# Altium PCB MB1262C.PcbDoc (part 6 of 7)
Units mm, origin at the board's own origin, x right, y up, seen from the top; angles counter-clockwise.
Board outline 208 x 250 mm, 6 copper layers (Top Layer, Layer 2, Layer 3, Layer 4, Layer 5, Bottom Layer), stack 1.596 mm thick; 483 components, 502 nets, 2134 pads, 1709 vias.
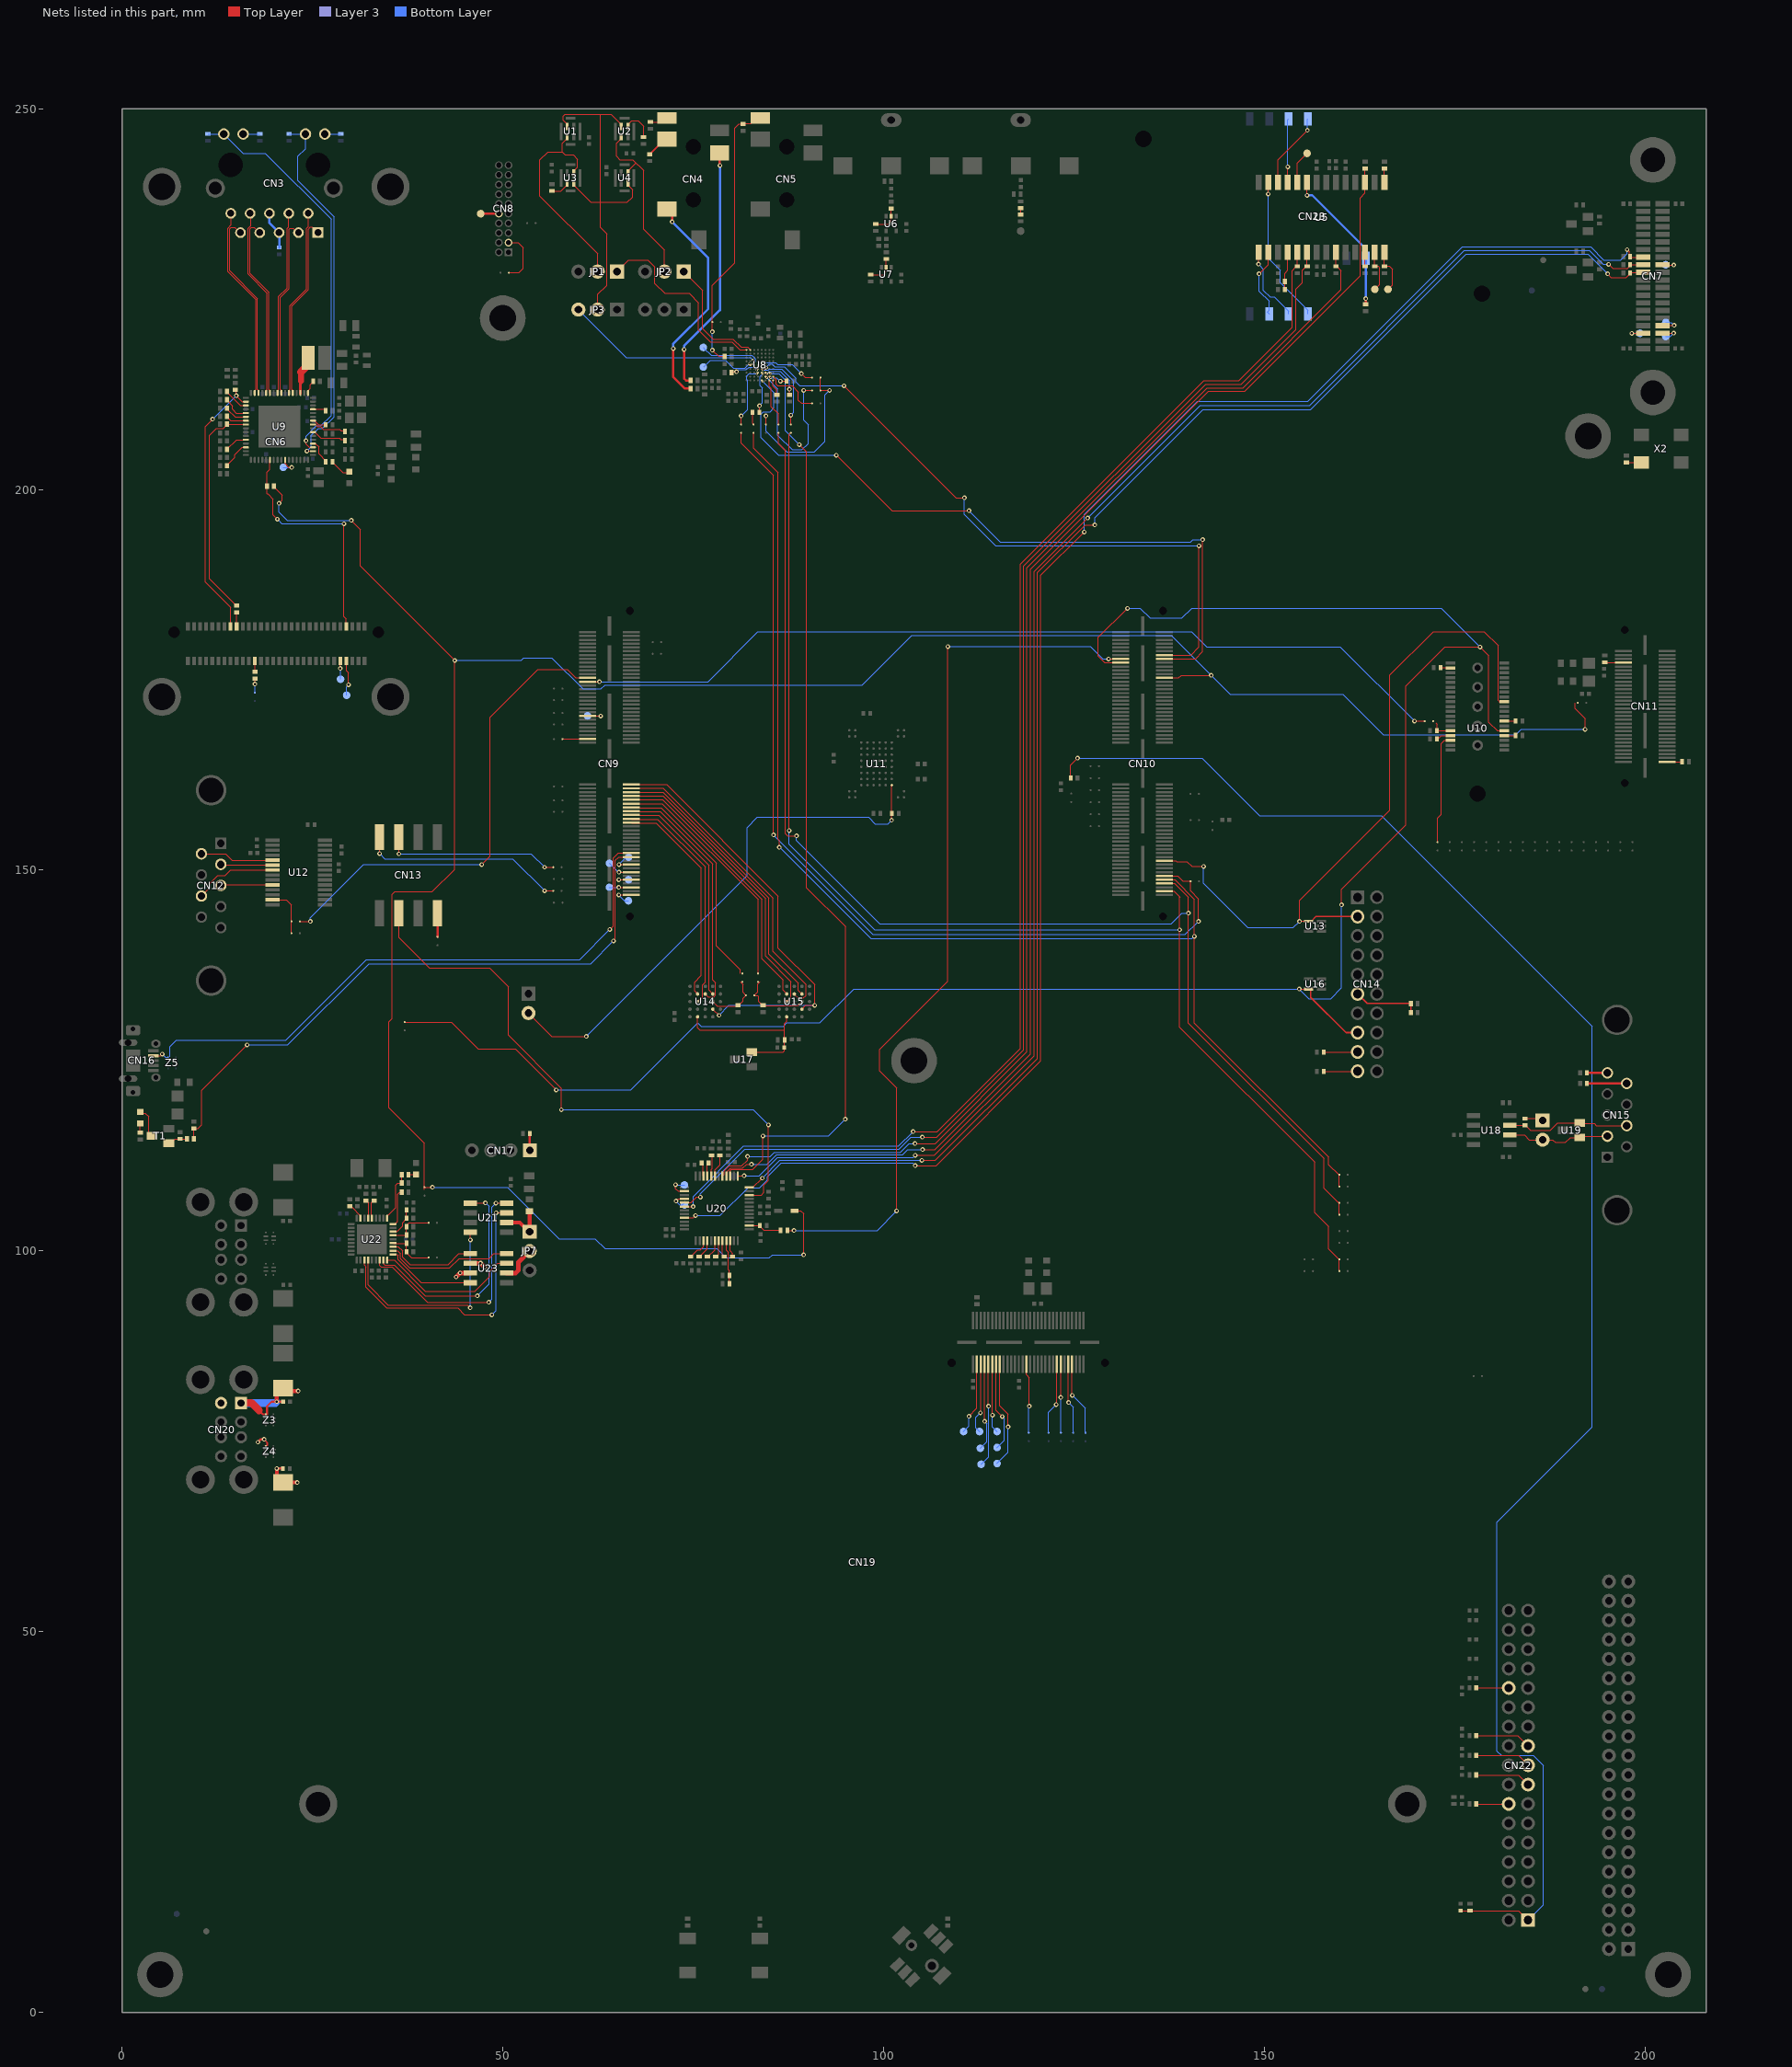
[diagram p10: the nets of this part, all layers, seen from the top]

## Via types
v1: diameter 0.6, hole 0.3, Top Layer to Bottom Layer, tented both sides, 979 vias
v2: diameter 0.55, hole 0.3, Top Layer to Bottom Layer, tented both sides, 687 vias
v3: diameter 0.3, hole 0.15, Top Layer to Bottom Layer, tented both sides, 31 vias
v4: diameter 0.4, hole 0.2, Top Layer to Bottom Layer, tented both sides, 12 vias

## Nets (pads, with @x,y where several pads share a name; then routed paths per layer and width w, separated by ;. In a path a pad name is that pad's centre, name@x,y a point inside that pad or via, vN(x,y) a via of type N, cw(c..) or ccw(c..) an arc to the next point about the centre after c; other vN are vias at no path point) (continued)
NetC102_1: C102.1 C105.2 CN20.T1 U23.7 Z3.1 | length 18.4
  Top Layer w0.1: v1(43.858,96.584) v1@43.858,96.6 ; v1(44.387,97.128) v1@44.401,97.114
  Top Layer w0.25: 17.97,79.08 18.488,78.562 Z3.1@18.892,78.562 ; 19.042,78.589 19.042,79.594 19.662,80.215 v1@20.33,80.215 ; v1(20.315,80.215) 20.318,80.219 C105.2@21.163,80.219
  Top Layer w0.5: v1@20.307,80.224 20.307,81.131 C102.1@21.17,81.995 21.555,81.609 23.121,81.609 v1(23.121,81.618)
  Top Layer w0.6: v1@43.858,96.6 v1(44.387,97.128) ; v1@44.401,97.114 U23.7@45.74,97.114
  Top Layer w1: CN20.T1@15.632,80.057 16.993,80.057 17.97,79.08
  Bottom Layer w1: CN20.T1@15.63,80.05 20.145,80.05 v1@20.285,80.19
NetC106_2: C106.2 C107.1 CN20.B1 U23.6 Z4.1 | length 9.4
  Top Layer w0.1: C107.1@20.321,70.462 C107.1@21.17,69.612 ; v1@47.076,98.384 v1(47.09,98.398) ; v1@47.636,97.852 v1(47.644,97.852)
  Top Layer w0.2: v1(18.664,75.271) 19.075,74.859 19.075,74.527 ; Z4.1@18.833,74.438 18.986,74.438 19.035,74.487 ; 19.075,74.68 19.075,74.527 ; 19.035,74.487 19.075,74.527 ; 19.035,74.487 19.075,74.487 19.075,74.527
  Top Layer w0.3: v1(17.852,74.901) 18.223,75.271 v1(18.664,75.271) ; v1(20.321,71.435) C106.2@21.119,71.435
  Top Layer w0.5: C107.1@20.321,70.462 v1(20.321,71.435) ; C107.1@21.17,69.612 v1(22.996,69.612)
  Top Layer w0.6: U23.6@45.74,98.384 v1@47.076,98.384 ; v1(47.09,98.398) v1@47.636,97.852
  Layer 3 w0.1: v1(47.09,98.398) v1@47.107,98.381
NetC118_2: C118.2 CN22.1 R83.2 R137.1 | length 222.8
  Top Layer w0.13: R83.2@124.559,162.096 124.559,163.811 v1(125.455,164.708) ; C118.2@175.731,13.369 C118.2@175.747,13.385 R137.1@176.98,13.385 183.39,13.385 CN22.1@184.62,12.155
  Bottom Layer w0.13: v1(125.455,164.708) 125.457,164.706 141.81,164.706 149.389,157.127 165.362,157.127 193.004,129.485 193.004,76.865 180.556,64.417 180.556,34.336 181.123,33.77 185.294,33.77 186.625,32.439 186.625,14.16 CN22.1@184.62,12.155
NetC120_2: C120.2 CN3.5 CN3.6 | length 5
  Bottom Layer w0.1: CN3.5@20.635,233.71 CN3.5@20.646,233.699
  Bottom Layer w0.3: CN3.6@19.365,236.25 19.365,234.98 CN3.5@20.635,233.71 ; C120.2@20.646,231.766 CN3.5@20.646,233.699
NetCN3_11: CN3.11 R140.1 | length 2.1
  Bottom Layer w0.1: CN3.11@26.63,246.66 26.65,246.68 R140.1@28.722,246.68
NetCN3_12: CN3.12 R141.2 U9.50 | length 48.8
  Top Layer w0.1: v1(24.282,205.032) 24.289,205.025 U9.50@25.075,205.025
  Bottom Layer w0.1: R141.2@21.929,246.68 24.07,246.68 CN3.12@24.09,246.66 24.09,244.744 23.078,243.732 23.078,240.558 27.833,235.803 27.833,209.54 26.316,208.023 25.776,208.023 24.83,207.076 24.83,205.58 v1(24.282,205.032)
NetCN3_13: CN3.13 R143.1 | length 2.2
  Bottom Layer w0.1: CN3.13@15.91,246.66 15.923,246.673 R143.1@18.096,246.673
NetCN3_14: CN3.14 R142.2 U9.51 | length 53.1
  Top Layer w0.1: v1(24.163,206.392) 24.163,205.977 24.615,205.525 U9.51@25.075,205.525
  Bottom Layer w0.1: R142.2@11.285,246.673 13.357,246.673 CN3.14@13.37,246.66 15.885,244.145 18.806,244.145 27.465,235.485 27.465,209.714 26.117,208.365 25.524,208.365 24.163,207.004 v1(24.163,206.392)
NetCN4_2: CN4.2 R1.2 | length 2.4
  Top Layer w0.127: R1.2@69.359,248.254 69.362,248.251 71.051,248.251 CN4.2@71.55,248.75
NetCN4_3: CN4.3 R4.1 | length 3.1
  Top Layer w0.2: R4.1@69.291,243.998 R4.1@69.297,244.004 ; R4.1@69.291,244.01 71.28,246 CN4.3@71.55,246
NetCN4_4: CN4.4 R42.2 | length 32.6
  Top Layer w0.2: CN4.4@78.45,244.2 CN4.4@78.493,244.157 ; v1@78.493,242.541 v1(78.507,242.527)
  Top Layer w0.3: v1(73.794,218.391) 73.794,214.571 74.052,214.313 R42.2@74.654,214.313 ; v1@78.493,242.541 CN4.4@78.493,244.157
  Bottom Layer w0.3: v1(73.794,218.391) 73.794,218.828 78.507,223.541 v1(78.507,242.527)
NetCN4_6: CN4.6 R46.2 | length 29.1
  Top Layer w0.2: CN4.6@71.55,236.8 CN4.6@72.215,236.135
  Top Layer w0.3: v1(72.215,235.138) CN4.6@72.215,236.135 ; v1(72.389,218.489) 72.389,214.756 73.907,213.238 R46.2@74.654,213.238
  Bottom Layer w0.3: v1(72.215,235.138) 76.967,230.387 76.967,223.707 72.389,219.129 v1(72.389,218.489)
NetCN5_2: CN5.2 R2.1 R35.2 SB3.1 | length 36.1
  Top Layer w0.127: v1(77.508,220.706) SB3.1@77.508,221.965 77.508,226.782 80.471,229.745 80.471,247.455 80.989,247.973 R2.1@81.535,247.973 81.6,248.038 82.578,248.038 83.125,248.585 CN5.2@83.811,248.585 ; v1(77.523,218.297) 78.346,217.475 R35.2@79.125,217.475
  Bottom Layer w0.127: v1(77.508,220.706) 77.523,220.691 v1(77.523,218.297)
NetCN6_18: CN6.18 R74.2 | length 1.9
  Top Layer w0.1: R74.2@15.046,183.861 15.051,183.856 15.051,182.001 CN6.18@15.05,182
NetCN6_23: CN6.23 R77.2 | length 1.4
  Top Layer w0.1: CN6.23@17.45,177.5 17.457,177.493 R77.2@17.457,176.065
NetCN6_51: CN6.51 TP13.1 | length 2.4
  Top Layer w0.1: v1(28.65,176.501) CN6.51@28.65,177.5
  Bottom Layer w0.1: v1(28.65,176.501) 28.7,176.451 TP13.1@28.7,175.075
NetCN6_53: CN6.53 TP14.1 | length 4.8
  Top Layer w0.1: CN6.53@29.45,177.5 29.473,177.523 CN6.53@29.522,177.474 ; CN6.53@29.479,177.431 29.479,176.19 29.756,175.913 v1(29.756,174.342)
  Bottom Layer w0.1: TP14.1@29.5,172.975 29.5,174.079 v1@29.771,174.349
NetCN7_15: CN7.15 R19.2 U20.33 | length 220.2
  Top Layer w0.1: U20.33@73.872,104.328 U20.33@73.85,104.35 75.007,104.35 v1(75.307,104.65) ; v1(104.138,111.221) 106.881,111.221 120.644,124.984 120.644,188.712 v1(126.343,194.411) ; v1(197.617,231.494) 197.931,231.179 197.931,230.669 R19.2@198.025,230.575 198.1,230.5 CN7.15@199.725,230.5
  Bottom Layer w0.1: v1(75.307,104.65) 78.508,104.65 82.183,108.325 83.699,108.325 84.729,109.355 84.729,109.738 86.531,111.54 103.819,111.54 v1(104.138,111.221) ; v1(126.343,194.411) 126.343,196.693 141.219,211.569 155.725,211.569 175.997,231.841 192.824,231.841 194.561,230.104 196.77,230.104 197.617,230.951 v1(197.617,231.494)
NetCN7_17: CN7.17 R21.2 U20.13 | length 207.7
  Top Layer w0.1: U20.13@80.85,109.85 80.889,109.889 80.896,109.882 v1(81.69,109.882) ; v1(104.159,112.57) 106.686,112.57 119.751,125.635 119.751,189.21 v1(126.797,196.256) ; v1(195.178,229.541) 195.719,229 197.604,229 197.624,228.98 198.025,229.381 R21.2@198.025,229.5 CN7.17@199.725,229.5
  Bottom Layer w0.1: v1(81.69,109.882) 83.666,109.882 86.082,112.298 103.887,112.298 v1(104.159,112.57) ; v1(126.797,196.256) 141.594,211.053 155.938,211.053 176.247,231.362 192.648,231.362 194.469,229.541 v1(195.178,229.541)
NetCN7_18: CN7.18 TP6.1 | length 2.6
  Top Layer w0.1: CN7.18@202.275,229.5 202.321,229.454 v1(203.749,229.454)
  Bottom Layer w0.1: TP6.1@202.675,229.5 202.721,229.454 v1(203.749,229.454)
NetCN7_19: CN7.19 R28.2 U20.12 | length 207.7
  Top Layer w0.1: U20.12@82.35,108.35 82.837,108.35 v1(84.053,109.566) ; v1(105.017,111.904) 106.81,111.904 120.204,125.298 120.204,189.087 126.455,195.339 v1(127.719,195.339) ; v1(195.074,228.301) 195.074,228.268 195.529,227.814 197.496,227.814 198.025,228.343 R28.2@198.025,228.425 198.1,228.5 CN7.19@199.725,228.5
  Bottom Layer w0.1: v1(84.053,109.566) 86.392,111.904 v1(105.017,111.904) ; v1(127.719,195.339) 127.719,196.288 141.91,210.479 156.052,210.479 176.483,230.911 192.464,230.911 v1(195.074,228.301)
NetCN7_34: CN7.34 TP7.1 | length 2.8
  Top Layer w0.1: CN7.34@202.275,221.5 202.315,221.54 v1(203.806,221.54)
  Bottom Layer w0.1: TP7.1@202.7,221.925 203.421,221.925 v1(203.806,221.54)
NetCN7_35: CN7.35 TP8.1 | length 2.5
  Top Layer w0.1: v1(198.247,220.483) 199.708,220.483 CN7.35@199.725,220.5
  Bottom Layer w0.1: v1(198.247,220.483) 198.265,220.5 TP8.1@199.3,220.5
NetCN7_36: CN7.36 TP9.1 | length 2.7
  Top Layer w0.1: CN7.36@202.275,220.5 202.299,220.524 v1(203.726,220.524)
  Bottom Layer w0.1: TP9.1@202.7,220.075 203.278,220.075 v1(203.726,220.524)
NetCN8_3: CN8.3 SB2.2 | length 7.1
  Top Layer w0.1: CN8.3@50.736,232.398 52.015,232.398 52.689,231.724 52.689,229.017 52.132,228.46 SB2.2@50.797,228.46
NetCN8_10: CN8.10 TP2.1 | length 2.3
  Top Layer w0.3: TP2.1@47.22,236.216 CN8.10@49.482,236.216
NetCN9_45: CN9.45 TP15.1 | length 3.5
  Top Layer w0.1: CN9.45@61.13,170.25 v1(62.853,170.25)
  Bottom Layer w0.1: TP15.1@61.125,170.275 62.828,170.275 v1(62.853,170.25)
NetCN9_104: CN9.104 TP16.1 | length 3.3
  Top Layer w0.1: v1(65.25,150.75) CN9.104@66.87,150.75
  Bottom Layer w0.1: v1@65.25,150.728 66.226,151.703 TP16.1@66.508,151.703
NetCN9_108: CN9.108 TP17.1 | length 3.4
  Top Layer w0.1: v1(65.247,149.75) CN9.108@66.87,149.75
  Bottom Layer w0.1: TP17.1@63.991,150.92 65.171,149.74 v1@65.266,149.74
NetCN9_112: CN9.112 TP18.1 | length 2.9
  Top Layer w0.1: v1(65.234,148.749) CN9.112@66.87,148.75
  Bottom Layer w0.1: v1@65.226,148.76 65.233,148.752 TP18.1@66.508,148.752
NetCN9_116: CN9.116 TP19.1 | length 2.9
  Top Layer w0.1: v1(65.233,147.75) CN9.116@66.87,147.75
  Bottom Layer w0.1: TP19.1@63.991,147.752 65.221,147.752 v1@65.234,147.74
NetCN9_120: CN9.120 TP20.1 | length 3.2
  Top Layer w0.1: v1(65.23,146.75) CN9.120@66.87,146.75
  Bottom Layer w0.1: v1@65.226,146.727 65.968,145.985 TP20.1@66.492,145.985
NetCN10_26: CN10.26 D1.2 R73.1 SB16.1 SB64.1 | length 345.4
  Top Layer w0.1: R73.1@19.936,200.412 19.936,200.362 21.044,199.254 21.044,198.601 v1(20.622,198.18) ; v1(30.096,195.94) 31.3,194.736 31.3,189.925 v1(43.686,177.539) 43.686,150.112 40.738,147.163 35.824,147.163 35.487,146.827 35.487,130.521 35.066,130.099 35.066,118.783 39.7,114.149 SB64.1@39.7,108.375 ; 39.7,108.075 SB64.1@39.7,108.375 ; v1(40.775,108.375) SB64.1@39.7,108.375 ; D1.2@88.32,105.3 89.1,105.3 89.5,104.9 v1(89.5,99.5) ; CN10.26@136.87,175.25 138.75,175.25 139.1,175.6 v1(143,175.6) ; 190.775,171.95 190.775,171.248 192.1,169.923 v1(192.1,168.5)
  Bottom Layer w0.1: v1(20.622,198.18) 20.622,197.042 21.712,195.953 30.083,195.953 v1(30.096,195.94) ; v1(40.775,108.375) 50.625,108.375 57.4,101.6 62.1,101.6 63.4,100.3 78.1,100.3 79.3,99.1 85,99.1 85.4,99.5 v1(89.5,99.5) ; v1(43.686,177.539) 52.423,177.539 52.735,177.851 56.449,177.851 60.5,173.8 62.9,173.8 63.4,174.3 97.2,174.3 103.7,180.8 137.8,180.8 145.5,173.1 160.3,173.1 165.6,167.8 183,167.8 183.7,168.5 v1(192.1,168.5)
NetCN11_1: CN11.1 R82.1 | length 2
  Top Layer w0.1: CN11.1@202.87,164.25 R82.1@204.85,164.25
NetCN11_54: CN11.54 R75.2 | length 2.5
  Top Layer w0.1: R75.2@194.675,177.3 194.725,177.25 CN11.54@197.13,177.25
NetCN12_2: CN12.2 U12.6 | length 6.8
  Top Layer w0.1: CN12.2@12.97,150.77 13.065,150.675 U12.6@19.75,150.675
NetCN12_3: CN12.3 U12.10 | length 6.8
  Top Layer w0.1: CN12.3@12.97,148 13.045,148.075 U12.10@19.75,148.075
NetCN12_6: CN12.6 U12.5 | length 9.7
  Top Layer w0.1: CN12.6@10.43,152.155 13.617,152.155 14.447,151.325 U12.5@19.75,151.325
NetCN12_8: CN12.8 U12.7 | length 11
  Top Layer w0.1: CN12.8@10.43,146.615 11.494,147.679 11.494,148.203 12.587,149.296 13.518,149.296 14.247,150.025 U12.7@19.75,150.025
NetCN13_1: CN13.1 SB54.2 | length 27
  Top Layer w0.1: v1(33.815,152.185) CN13.1@33.815,154.35 ; v1(55.486,147.292) SB54.2@56.617,147.292
  Bottom Layer w0.1: v1(33.815,152.185) 34.5,151.5 51.278,151.5 v1(55.486,147.292)
NetCN13_3: CN13.3 SB51.2 | length 23.2
  Top Layer w0.1: v1(36.355,152.145) CN13.3@36.355,154.35 ; v1(55.486,150.392) SB51.2@56.617,150.392
  Bottom Layer w0.1: v1(36.355,152.145) 53.732,152.145 v1(55.486,150.392)
NetCN13_4: CN13.4 U20.10 | length 78.5
  Top Layer w0.1: CN13.4@36.355,144.35 36.355,141.175 40.382,137.147 48.261,137.147 50.741,134.667 50.741,128.321 57.689,121.373 v1(57.689,118.554) ; U20.10@82.35,107.35 83.949,107.35 84.277,107.678 84.277,108.678 84.872,109.274 v1(84.872,116.568)
  Bottom Layer w0.1: v1(57.689,118.554) 82.885,118.554 v1(84.872,116.568)
NetCN13_8: CN13.8 SB58.1 | length 3.1
  Top Layer w0.1: CN13.8@41.425,144.34 CN13.8@41.435,144.35
  Top Layer w0.3: SB58.1@41.425,141.25 CN13.8@41.425,144.34
NetCN14_11: CN14.11 R86.2 R89.1 | length 8.7
  Top Layer w0.2: CN14.11@162.23,133.755 163.485,132.5 R86.2@169.225,132.5 R89.1@169.225,131.3
NetCN14_17: CN14.17 R91.1 | length 4.5
  Top Layer w0.1: R91.1@157.775,126.125 162.22,126.125 CN14.17@162.23,126.135
NetCN14_19: CN14.19 R92.1 | length 4.5
  Top Layer w0.1: R92.1@157.775,123.575 162.21,123.575 CN14.19@162.23,123.595
NetCN15_2: CN15.2 JP6.2 U18.6 U19.1 | length 13.6
  Top Layer w0.1: U18.6@182.2,115.24 184.15,115.24 184.785,114.605 JP6.2@186.525,114.605 187.83,114.605 188.177,114.257 189.541,114.257 190.183,114.9 U19.1@191.4,114.9 191.58,115.08 CN15.2@195.03,115.08
NetCN15_5: CN15.5 R93.2 | length 2.7
  Top Layer w0.1: CN15.5@195.02,123.4 CN15.5@195.03,123.39
  Top Layer w0.3: R93.2@192.35,123.4 CN15.5@195.02,123.4
NetCN15_7: CN15.7 R96.1 U18.7 U19.2 | length 16.2
  Top Layer w0.1: U18.7@182.2,116.51 182.21,116.5 R96.1@184.2,116.5 184.293,116.5 184.944,115.849 187.53,115.849 188.48,116.8 U19.2@191.4,116.8 191.474,116.726 193.321,116.726 193.582,116.465 CN15.7@197.57,116.465
NetCN15_9: CN15.9 R94.2 | length 5.2
  Top Layer w0.1: CN15.9@197.565,122 CN15.9@197.57,122.005
  Top Layer w0.3: R94.2@192.35,122 CN15.9@197.565,122
NetCN17_1: CN17.1 R99.1 | length 2.2
  Top Layer w0.3: R99.1@53.547,115.42 53.547,113.232 CN17.1@53.56,113.219
NetCN19_8: CN19.8 SB78.1 | length 9.8
  Top Layer w0.1: 124.738,83.061 124.75,83.072 ; CN19.8@124.75,85.13 124.75,83.072 ; v1(124.775,81.051) 124.75,81.075 124.75,83.072
  Bottom Layer w0.1: v1(124.775,81.051) 126.479,79.346 126.479,76.171 SB78.1@126.525,76.125
NetCN19_10: CN19.10 SB79.1 | length 9.3
  Top Layer w0.1: CN19.10@124.239,85.162 124.25,85.152 124.25,80.138 v1(124.285,80.103)
  Bottom Layer w0.1: v1(124.285,80.103) 124.9,79.488 SB79.1@124.9,76.125
NetCN19_14: CN19.14 SB80.1 | length 9
  Top Layer w0.1: CN19.14@123.234,85.12 123.25,85.104 123.25,80.808 v1(123.273,80.784)
  Bottom Layer w0.1: v1(123.273,80.784) 123.275,80.783 SB80.1@123.275,76.125
NetCN19_16: CN19.16 SB81.1 | length 9.5
  Top Layer w0.1: v1(122.656,79.847) 122.75,79.942 122.75,85.133 CN19.16@122.735,85.148
  Bottom Layer w0.1: SB81.1@121.65,76.125 121.65,78.842 v1(122.656,79.847)
NetCN19_32: CN19.32 SB82.1 | length 9.2
  Top Layer w0.1: CN19.32@118.75,85.13 118.75,83.757 119.121,83.386 119.121,81.338 119.12,81.337 v1(119.12,79.623)
  Bottom Layer w0.1: SB82.1@119.05,76.125 119.05,79.553 v1(119.12,79.623)
NetCN19_46: CN19.46 TP29.1 | length 14.3
  Top Layer w0.1: 115.25,83.13 115.25,79.671 116.355,78.566 v1(116.355,76.913) ; CN19.46@115.25,85.13 115.25,82.923 115.263,82.911
  Bottom Layer w0.1: TP29.1@114.9,72.1 116.355,73.555 v1(116.355,76.913)
NetCN19_48: CN19.48 TP27.1 | length 11.8
  Top Layer w0.1: CN19.48@114.75,85.168 114.75,79.095 v1(115.576,78.269)
  Bottom Layer w0.1: TP27.1@114.9,74.2 115.873,75.173 115.873,77.972 v1(115.576,78.269)
NetCN19_50: CN19.50 TP24.1 | length 9.1
  Top Layer w0.1: CN19.50@114.25,85.108 114.25,78.504 v1(114.297,78.457)
  Bottom Layer w0.1: v1(114.297,78.457) 114.297,76.903 TP24.1@114.9,76.3
NetCN19_52: CN19.52 TP30.1 | length 13.5
  Top Layer w0.1: CN19.52@113.75,85.094 113.75,79.659 v1(113.767,79.641)
  Bottom Layer w0.1: TP30.1@112.8,72 113.767,72.967 v1(113.767,79.641)
NetCN19_54: CN19.54 TP28.1 | length 11.4
  Top Layer w0.1: CN19.54@113.25,85.08 113.25,77.633 v1(113.253,77.63)
  Bottom Layer w0.1: TP28.1@112.7,74.1 113.538,74.938 113.538,77.344 v1(113.253,77.63)
NetCN19_56: CN19.56 TP25.1 | length 9.3
  Top Layer w0.1: v1(112.707,78.753) 112.75,78.796 CN19.56@112.75,85.166
  Bottom Layer w0.1: TP25.1@112.6,76.3 112.097,76.803 112.097,78.143 v1(112.707,78.753)
NetCN19_58: CN19.58 TP26.1 | length 9.5
  Top Layer w0.1: v1(111.206,78.304) 112.25,79.347 CN19.58@112.25,85.086
  Bottom Layer w0.1: TP26.1@110.5,76.3 111.206,77.006 v1(111.206,78.304)
NetCN22_14: CN22.14 R136.1 | length 4.3
  Top Layer w0.1: R136.1@177.818,27.394 177.819,27.395 CN22.14@182.08,27.395
NetCN22_15: CN22.15 R134.2 | length 7.3
  Top Layer w0.1: R134.2@177.818,31.201 177.819,31.203 183.352,31.203 CN22.15@184.62,29.935
NetCN22_17: CN22.17 R133.2 | length 7.3
  Top Layer w0.1: R133.2@177.818,33.765 177.824,33.758 183.337,33.758 CN22.17@184.62,32.475
NetCN22_19: CN22.19 R132.2 | length 7.4
  Top Layer w0.1: R132.2@177.818,36.38 177.823,36.384 183.251,36.384 CN22.19@184.62,35.015
NetCN22_26: CN22.26 R131.1 | length 4.3
  Top Layer w0.1: R131.1@177.818,42.644 177.827,42.635 CN22.26@182.08,42.635
NetCN23_C2: CN23.C2 U5.16 | length 8.7
  Top Layer w0.1: v1(149.299,228.319) 149.318,228.319 150.515,229.515 U5.16@150.515,230.489
  Bottom Layer w0.1: v1(149.299,228.319) 149.299,226.025 150.617,224.707 150.617,223.507 150.38,223.27 CN23.C2@150.62,223.03
NetCN23_C3: CN23.C3 U5.15 | length 10.1
  Top Layer w0.1: v1(149.238,229.582) 149.245,229.589 U5.15@149.245,231.135
  Bottom Layer w0.1: v1(149.238,229.582) 149.238,229.557 149.875,228.921 149.875,226.132 150.753,225.253 151.323,225.253 153.16,223.416 CN23.C3@153.16,223.03
NetCN23_C4: CN23.C4 U5.13 | length 19.4
  Top Layer w0.1: v1(150.5,238.8) 150.515,238.815 U5.13@150.515,240.315
  Bottom Layer w0.1: v1(150.5,238.8) 150.5,230.38 152.075,228.805 152.075,227.149 155.7,223.524 CN23.C4@155.7,223.03
NetCN23_C7: CN23.C7 U5.11 | length 8.4
  Top Layer w0.1: U5.11@153.055,240.315 153.064,240.324 v1(153.064,242.345)
  Bottom Layer w0.1: v1(153.064,242.345) 153.064,248.556 153.055,248.565 CN23.C7@153.16,248.67
NetCN23_C8: CN23.C8 U5.12 | length 10
  Top Layer w0.1: U5.12@151.785,240.315 151.785,243.287 v1(155.647,247.15)
  Bottom Layer w0.1: v1(155.647,247.15) 155.647,248.617 CN23.C8@155.7,248.67
NetCN23_S2: CN23.S2 R32.2 U5.9 | length 19.8
  Top Layer w0.1: v1(155.595,238.605) U5.9@155.595,240.315
  Top Layer w0.3: R32.2@163.298,224.305 v1(163.298,225.04)
  Bottom Layer w0.1: CN23.S2@163.32,230.36 163.325,230.355 CN23.S2@163.325,230.268
  Bottom Layer w0.3: v1@155.476,238.628 156.272,238.628 163.32,231.58 CN23.S2@163.32,230.36 ; v1(163.298,225.04) 163.298,230.295 163.325,230.268 CN23.S2@163.339,230.254
NetJP1_1: JP1.1 U8.A9 | length 25.9
  Top Layer w0.1: JP1.1@64.995,228.607 66.521,230.134 69.022,230.134 69.961,229.194 69.961,227.051 71.264,225.749 74.466,225.749 75.704,224.51 75.704,220.911 77.256,219.36 80.093,219.36 81.127,218.325 U8.A9@82,218.325
NetJP1_2: JP1.2 U1.4 U3.4 | length 27.8
  Top Layer w0.127: U1.4@58.438,246.325 58.438,246.079 57.811,245.452 57.811,244.298 ; U3.4@59.338,241.579 59.338,241.829 59.829,242.32 59.829,243.357 59.256,243.93 58.178,243.93 57.811,244.298 ; JP1.2@62.455,228.607 62.455,230.947 54.873,238.529 54.873,243.251 55.92,244.298 57.811,244.298
NetJP2_1: JP2.1 U8.B9 | length 15.9
  Top Layer w0.1: JP2.1@73.764,228.607 76.218,226.153 76.218,221.132 77.625,219.725 80.23,219.725 81.28,218.675 82.15,218.675 U8.B9@82.5,218.325
NetJP2_2: JP2.2 U2.4 U4.4 | length 23.3
  Top Layer w0.127: U2.4@65.55,246.325 65.55,246.05 64.922,245.422 64.922,243.753 65.37,243.305 67.067,243.305 68.489,241.883 68.489,234.154 71.224,231.418 JP2.2@71.224,228.607 ; U4.4@66.45,241.579 66.45,241.848 67.474,242.872
NetJP3_2: JP3.2 U1.3 U2.3 U3.3 U4.3 | length 48
  Top Layer w0.127: U1.3@58.438,247.675 58.438,247.962 57.909,248.491 57.909,249.014 58.177,249.282 62.82,249.282 ; U3.3@59.338,240.229 59.338,239.863 59.367,239.892 61.549,237.71 62.82,237.71 ; JP3.2@62.455,223.607 62.455,225.629 63.643,226.817 63.643,233.556 62.82,234.379 62.82,237.71 ; U2.3@65.55,247.675 65.55,247.917 64.185,249.282 62.82,249.282 ; U4.3@66.45,240.229 66.45,239.942 67.026,239.366 67.026,238.387 66.349,237.71 62.82,237.71 ; 62.82,237.71 62.82,249.282
NetJP3_3: JP3.3 U8.C6 | length 25.9
  Top Layer w0.2: v3(82.84,216.985) U8.C6@83,216.825
  Bottom Layer w0.1: JP3.3@59.915,223.607 66.186,217.336 82.489,217.336 v3(82.84,216.985)
NetJP5_2: JP5.2 R85.1 U11.C3 | length 70.1
  Top Layer w0.1: JP5.2@53.37,131.24 56.435,128.174 v1(60.963,128.174) ; JP5.2@53.876,130.883 JP5.2@53.876,131.245 ; v1(101.051,156.566) 101.051,157.426 R85.1@101.075,157.45 U11.C3@101.075,161.175
  Bottom Layer w0.1: v1(60.963,128.174) 82.072,149.283 82.072,155.587 83.437,156.952 98.03,156.952 98.896,156.087 100.571,156.087 v1(101.051,156.566)
NetJP6_1: JP6.1 R96.2 | length 2.4
  Top Layer w0.1: R96.2@184.2,117.4 186.27,117.4 JP6.1@186.525,117.145
NetJP7_1: JP7.1 L7.2 U21.2 | length 6
  Top Layer w0.5: U21.2@50.49,103.752 52.24,103.752 JP7.1@53.4,102.593 ; L7.2@53.514,105.171 53.522,105.163 JP7.1@53.522,102.54
NetJP7_2: JP7.2 U23.2 | length 4.9
  Top Layer w0.6: U23.2@50.49,97.114 51.699,97.114 52.058,97.474 52.058,98.554 JP7.2@53.514,100.01
NetLD1_2: LD1.2 R70.2 | length 2.9
  Top Layer w0.1: R70.2@27.637,203.634 27.637,203.585 29.032,202.19 LD1.2@29.913,202.19
NetLD2_1: LD2.1 R100.1 | length 1.2
  Top Layer w0.1: R100.1@2.384,115.547 R100.1@2.395,115.559
  Top Layer w0.15: R100.1@2.395,115.559 LD2.1@2.395,116.764
NetLD2_2: LD2.2 T1.3 | length 4.1
  Top Layer w0.15: LD2.2@2.395,118.264 2.572,118.088 3.057,118.088 3.513,117.632 3.513,115.543 T1.3@3.945,115.111
NetLD3_1: LD3.1 R107.2 | length 1
  Top Layer w0.1: R107.2@37.625,110.015 37.652,110.042 LD3.1@38.59,110.042
NetLE1_1: LE1.1 U9.3 | length 5.1
  Top Layer w0.1: LE1.1@24.222,217.061 LE1.1@24.44,217.278
  Top Layer w0.35: U9.3@23.439,212.56 23.439,214.194
  Top Layer w0.5: 23.439,214.194 23.503,214.257
  Top Layer w0.8: 23.503,214.257 23.503,215.396
  Top Layer w1: 23.503,215.396 24.222,216.116 LE1.1@24.222,217.061
NetR3_1: R3.1 U2.2 | length 4.2
  Top Layer w0.127: U2.2@66.45,247.675 66.45,247.95 66.917,248.417 67.755,248.417 68.475,247.697 R3.1@68.475,246.25
NetR5_2: R5.2 U5.3 U20.16 | length 184.1
  Top Layer w0.1: U20.16@79.35,109.85 79.35,110.348 79.899,110.897 81.501,110.897 82,111.396 v1(82.657,111.396) ; v1(105.104,113.32) 106.702,113.32 119.282,125.899 119.282,189.508 142.642,212.868 147.43,212.868 162.593,228.031 162.593,238.279 163.215,238.901 U5.3@163.215,240.315 163.215,242.115 R5.2@163.225,242.125
  Bottom Layer w0.1: v1(82.657,111.396) 84.67,111.396 85.926,112.652 102.496,112.652 103.164,113.32 v1(105.104,113.32)
NetR6_1: R6.1 U5.1 | length 1.8
  Top Layer w0.1: R6.1@165.75,242.125 165.755,242.12 U5.1@165.755,240.315
NetR8_1: R8.1 U3.2 | length 2.6
  Top Layer w0.127: R8.1@56.448,239.185 57.659,239.185 58.438,239.964 U3.2@58.438,240.229
NetR10_1: R10.1 R13.2 | length 0.8
  Top Layer w0.1: R13.2@118,236.1 R10.1@118,236.925
NetR11_2: R11.2 R15.1 U6.2 | length 3.8
  Top Layer w0.1: R15.1@98.95,234.85 100.615,234.85 101,235.235 U6.2@101,235.85 R11.2@101,236.875
NetR18_2: R18.2 R29.1 U7.2 | length 3.9
  Top Layer w0.1: R29.1@98.3,228.2 99.938,228.2 100.35,228.612 U7.2@100.35,229.2 R18.2@100.35,230.25
NetR22_1: R22.1 U5.19 U20.30 | length 175.8
  Top Layer w0.1: U20.30@73.85,105.85 v1(74.993,105.85) ; v1(103.862,115.691) 107.049,115.691 117.961,126.603 117.961,190.197 142.066,214.302 146.664,214.302 153.645,221.283 153.645,228.746 154.199,229.3 R22.1@154.325,229.3 U5.19@154.325,231.135
  Bottom Layer w0.1: v1(74.993,105.85) 74.993,107.156 81.619,113.782 101.953,113.782 v1(103.862,115.691)
NetR23_1: R23.1 U5.20 U20.29 | length 176.1
  Top Layer w0.1: U20.29@73.85,106.35 74.711,106.35 75.43,107.07 v1(75.931,107.07) ; v1(105.093,114.952) 106.966,114.952 118.401,126.387 118.401,189.949 142.279,213.826 146.967,213.826 154.115,220.974 154.115,226.285 154.962,227.132 154.962,228.761 155.502,229.3 R23.1@155.6,229.3 155.6,231.13 U5.20@155.595,231.135
  Bottom Layer w0.1: v1(75.931,107.07) 75.931,107.509 81.803,113.381 102.034,113.381 103.605,114.952 v1(105.093,114.952)
NetR24_2: R24.2 U5.23 U20.17 | length 172.4
  Top Layer w0.1: U20.17@78.85,109.85 79.05,110.05 79.05,110.512 79.708,111.17 81.385,111.17 82.144,111.928 v1(82.144,112.414) ; v1(104.118,114.12) 106.772,114.12 118.83,126.178 118.83,189.689 142.484,213.342 147.164,213.342 160.079,226.257 160.079,228.71 159.489,229.3 R24.2@159.4,229.3 159.4,231.13 U5.23@159.405,231.135
  Bottom Layer w0.1: v1(82.144,112.414) 85.086,112.414 85.642,112.97 102.209,112.97 103.359,114.12 v1(104.118,114.12)
NetR25_1: R25.1 U5.26 | length 1.8
  Top Layer w0.1: U5.26@163.215,231.135 163.225,231.125 R25.1@163.225,229.3
NetR26_2: R26.2 TP4.1 U5.27 | length 5.6
  Top Layer w0.1: U5.27@164.485,231.135 164.485,229.315 R26.2@164.5,229.3 164.932,229.3 165.13,229.102 165.13,226.905 TP4.1@164.5,226.275
NetR27_2: R27.2 TP5.1 U5.28 | length 5.9
  Top Layer w0.1: R27.2@165.75,229.3 R27.2@165.755,229.305 ; U5.28@165.755,231.135 R27.2@165.755,229.305 ; TP5.1@166.225,226.275 166.802,226.852 166.802,228.877 166.374,229.305 R27.2@165.755,229.305
NetR30_1: R30.1 R31.2 U5.18 | length 5
  Top Layer w0.1: R31.2@152.675,226.25 R30.1@152.675,227.3 152.675,228.381 153.055,228.761 U5.18@153.055,231.135
NetR40_2: R40.2 U8.D4 U8.D5 | length 4.5
  Top Layer w0.1: R40.2@80.025,215.35 80.039,215.336 80.15,215.448 v1(80.674,215.448)
  Top Layer w0.15: U8.D4@83.5,215.825 U8.D5@83.5,216.325
  Top Layer w0.2: v3(83.34,215.665) U8.D4@83.5,215.825
  Bottom Layer w0.1: v1(80.674,215.448) 80.94,215.714 81.963,215.714 82.315,216.066 82.939,216.066 v3(83.34,215.665)
NetR43_1: R43.1 U8.G2 | length 2.5
  Top Layer w0.127: v1(86.442,214.207) 86.456,214.22 R43.1@87.261,214.22
  Top Layer w0.2: U8.G2@85,214.825 v3(85.16,214.665)
  Bottom Layer w0.1: v3@85.16,214.675 85.974,214.675 v1(86.442,214.207)
NetR44_2: R44.2 U9.1 | length 1.8
  Top Layer w0.1: U9.1@24.425,212.675 24.425,212.931 24.729,213.236 24.729,213.734 25.094,214.098 R44.2@25.094,214.182
NetR48_2: R48.2 U9.19 | length 3.3
  Top Layer w0.13: R48.2@13.775,212.875 13.775,212.786 15.536,211.025 U9.19@16.275,211.025
NetR49_1: R49.1 U8.H1 | length 2.1
  Top Layer w0.1: U8.H1@85.5,214.325 85.5,213.557 85.98,213.077 R49.1@85.98,212.425
  Top Layer w0.2: R49.1@85.98,212.376 R49.1@85.98,212.425
NetR50_1: R50.1 U8.F3 | length 5.7
  Top Layer w0.127: v1(87.628,213.161) 87.628,212.429 R50.1@87.633,212.425
  Top Layer w0.2: U8.F3@84.5,215.325 v3(84.66,215.165)
  Bottom Layer w0.1: v3(84.66,215.165) 84.97,215.475 86.425,215.475 87.628,214.272 v1(87.628,213.161)
NetR51_2: R51.2 U9.21 | length 3.5
  Top Layer w0.13: R51.2@13.775,211.775 13.825,211.725 13.825,211.667 14.5,210.992 14.5,210.531 15.006,210.025 U9.21@16.275,210.025
NetR52_2: R52.2 U9.22 | length 3.1
  Top Layer w0.13: R52.2@13.775,210.675 13.85,210.625 13.875,210.65 13.875,210.5 14.85,209.525 U9.22@16.275,209.525
NetR53_2: R53.2 U9.61 | length 1.7
  Top Layer w0.1: U9.61@25.075,210.525 26.536,210.525 R53.2@26.739,210.321
NetR54_1: R54.1 SB11.2 | length 1.6
  Top Layer w0.1: R54.1@82.792,210.125 82.792,208.665 SB11.2@82.923,208.534
NetR54_2: R54.2 U8.E3 | length 5.7
  Top Layer w0.1: R54.2@83.692,210.125 83.692,210.97 v1(83.715,210.993)
  Top Layer w0.2: U8.E3@84,215.325 v3(84.16,215.165)
  Bottom Layer w0.1: v1(83.715,210.993) 84.1,211.378 84.1,213.3 83.8,213.6 83.8,214.825 v3@84.15,215.175
NetR55_2: R55.2 U9.23 | length 2.9
  Top Layer w0.13: R55.2@13.775,209.6 13.775,209.521 14.246,209.05 16.325,209.05 U9.23@16.275,209.025
NetR57_2: R57.2 U9.58 | length 1.9
  Top Layer w0.1: U9.58@25.075,209.025 25.287,209.025 25.814,208.499 26.736,208.499 R57.2@26.737,208.497
NetR58_1: R58.1 U9.57 | length 4.7
  Top Layer w0.1: U9.57@25.075,208.525 25.368,208.525 25.674,208.219 26.107,208.219 26.413,207.914 28.56,207.914 28.745,207.729 29.322,207.729 R58.1@29.391,207.66
NetR61_1: R61.1 U9.55 | length 4.7
  Top Layer w0.1: U9.55@25.075,207.525 25.305,207.525 26.092,206.738 28.558,206.738 28.727,206.569 29.131,206.569 R61.1@29.287,206.413
NetR67_2: R67.2 X2.1 | length 1.8
  Top Layer w0.1: R67.2@197.632,203.545 197.637,203.55 X2.1@199.48,203.55
NetR70_1: R70.1 U9.52 | length 3.2
  Top Layer w0.1: U9.52@25.075,206.025 25.391,206.025 25.834,205.582 25.834,204.683 26.737,203.779 R70.1@26.737,203.734
NetR76_1: R76.1 U10.36 | length 1.4
  Top Layer w0.1: R76.1@173.138,176.613 173.138,176.58 U10.36@174.44,176.58 ; U10.36@174.455,176.565 U10.36@174.44,176.58 ; U10.36@174.47,176.58 U10.36@174.44,176.58
NetR77_1: R77.1 SB77.2 | length 1.9
  Top Layer w0.1: R77.1@17.457,175.165 17.457,174.45 v1(17.463,174.444)
  Bottom Layer w0.1: SB77.2@17.457,173.309 17.457,174.438 v1(17.463,174.444)
NetR78_2: R78.2 U10.13 | length 1.4
  Top Layer w0.1: U10.13@181.53,169.595 182.906,169.595 R78.2@182.914,169.602
NetR79_1: R79.1 SB18.1 U10.10 | length 2.9
  Top Layer w0.1: 172.472,169.346 172.65,169.167 R79.1@172.65,168.325 ; R79.1@172.651,168.259 172.717,168.325 U10.10@174.47,168.325
NetR80_2: R80.2 U10.7 | length 1.5
  Top Layer w0.1: U10.7@181.53,167.69 182.866,167.69 R80.2@182.953,167.777
NetR81_1: R81.1 U10.8 | length 2
  Top Layer w0.1: R81.1@172.71,167.208 173.192,167.69 U10.8@174.47,167.69
NetR87_2: R87.2 SB60.2 SB61.1 U15.C2 | length 9.6
  Top Layer w0.1: 83.808,135.344 83.503,135.04 83.503,134.055 SB61.1@83.015,133.566 83.477,133.566 83.586,133.456 83.586,132.744 84.095,132.235 84.151,132.235 R87.2@84.187,132.27 84.222,132.235 88.76,132.235 U15.C2@89.275,132.75
NetR88_2: R88.2 SB59.2 SB61.2 U14.C2 | length 7.6
  Top Layer w0.1: U14.C2@77.575,132.75 78.144,132.181 81.092,132.181 81.181,132.27 81.181,132.439 81.549,132.808 81.549,133.2 SB61.2@81.915,133.566 81.519,133.961 81.519,134.98 81.155,135.344
NetR98_1: R98.1 R102.2 T1.1 | length 2.6
  Top Layer w0.1: T1.1@6.145,114.161 6.393,114.161 6.947,114.714 R98.1@7.621,114.714 8.532,114.714 R102.2@8.537,114.72
NetR103_1: R103.1 U20.20 | length 2.8
  Top Layer w0.1: U20.20@77.35,109.85 77.35,110.701 77.473,110.824 77.473,112.477 R103.1@77.4,112.55
NetR104_1: R104.1 U20.19 | length 3
  Top Layer w0.1: U20.19@77.85,109.85 77.85,110.662 78.5,111.312 R104.1@78.5,112.55
NetR106_1: R106.1 U20.21 | length 1.8
  Top Layer w0.1: U20.21@76.85,109.85 76.85,111.384 R106.1@77.015,111.549
NetR106_2: R106.2 U20.22 | length 1.8
  Top Layer w0.1: R106.2@76.115,111.549 76.304,111.36 76.304,109.896 U20.22@76.35,109.85
NetR107_1: R107.1 R108.2 U22.28 | length 7
  Top Layer w0.1: U22.28@34.825,104.3 34.825,104.583 35.927,105.684 35.927,108.652 36.175,108.9 R108.2@36.725,108.9 ; R108.2@36.725,108.77 R107.1@36.725,110.015
NetR109_2: R109.2 U22.27 | length 5
  Top Layer w0.1: U22.27@35.575,103.55 35.845,103.55 36.206,103.911 36.206,107.431 36.45,107.675 R109.2@36.7,107.675 ; R109.2@36.712,107.657 R109.2@36.712,107.736
NetR110_2: R110.2 U22.33 | length 2.5
  Top Layer w0.1: R110.2@32.012,106.602 32.079,106.602 32.384,106.297 32.384,104.359 U22.33@32.325,104.3
NetR111_2: R111.2 U22.32 | length 2.5
  Top Layer w0.1: U22.32@32.825,104.3 32.75,104.375 32.75,106.362 32.927,106.539 33,106.539 R111.2@33.063,106.602
NetR112_1: R112.1 U22.35 | length 2
  Top Layer w0.1: R112.1@30.128,105.829 31.325,104.632 U22.35@31.325,104.3
NetR114_2: R114.2 R115.1 U22.25 | length 3.9
  Top Layer w0.1: U22.25@35.575,102.55 36.109,102.55 36.834,103.275 36.834,103.718 37.356,104.24 R115.1@37.356,104.305 R114.2@37.356,105.405
NetR116_2: R116.2 R118.2 U20.2 | length 4.5
  Top Layer w0.1: U20.2@82.35,103.35 82.36,103.34 R116.2@83.76,103.34 83.76,103.197 84.24,102.717 86.468,102.717 R118.2@86.475,102.71
NetR117_2: R117.2 R119.1 SB68.2 U22.24 | length 6.1
  Top Layer w0.1: U22.24@35.575,102.05 35.63,102.105 R119.1@37.356,102.105 R117.2@37.356,103.205 37.356,103.364 37.719,103.728 40.239,103.728 SB68.2@40.255,103.712
NetR120_1: R120.1 R121.2 SB71.2 U22.22 | length 6.2
  Top Layer w0.1: U22.22@35.575,101.05 35.62,101.005 R120.1@37.356,101.005 R121.2@37.356,99.905 37.356,99.783 38,99.14 40.237,99.14 SB71.2@40.255,99.157
NetR122_1: R122.1 U20.39 | length 3
  Top Layer w0.1: R122.1@74.66,99.273 74.726,99.273 75.588,100.135 75.899,100.135 76.35,100.586 U20.39@76.35,101.35
NetR123_1: R123.1 U20.40 | length 2.6
  Top Layer w0.1: R123.1@75.76,99.273 75.862,99.273 76.85,100.261 U20.40@76.85,101.35
NetR124_2: R124.2 U20.42 | length 2.5
  Top Layer w0.1: R124.2@76.86,99.273 76.951,99.273 77.85,100.172 U20.42@77.85,101.35
NetR125_2: R125.2 U20.43 | length 2.3
  Top Layer w0.1: R125.2@77.96,99.273 78.029,99.273 78.35,99.593 U20.43@78.35,101.35
NetR126_2: R126.2 U20.44 | length 2.2
  Top Layer w0.1: U20.44@78.85,101.35 78.85,99.482 R126.2@79.06,99.273
NetR127_2: R127.2 U20.46 | length 2.2
  Top Layer w0.1: U20.46@79.85,101.35 79.85,99.995 80.16,99.685 R127.2@80.16,99.273
NetR128_1: R128.1 R129.1 U20.45 | length 5.8
  Top Layer w0.1: U20.45@79.35,101.35 79.35,100.071 79.607,99.814 79.607,97.551 79.76,97.398 R128.1@79.76,96.798 R129.1@79.76,95.698
NetSB4_1: SB4.1 SB5.1 SB8.2 | length 22.5
  Top Layer w0.1: SB8.2@84.556,208.534 v1(84.556,209.66) ; SB4.1@91.7,214.7 SB5.1@91.7,213 v1(92.9,213)
  Bottom Layer w0.1: v1(84.556,209.66) 84.556,207.644 87.3,204.9 90.9,204.9 92.3,206.3 92.3,212.4 v1(92.9,213)
NetSB4_2: SB4.2 U8.E5 | length 7.6
  Top Layer w0.1: v1(89.2,215.2) 89.7,214.7 SB4.2@90.6,214.7
  Top Layer w0.2: U8.E5@84,216.325 v3(84.16,216.485)
  Bottom Layer w0.1: v3(84.16,216.485) 84.34,216.665 85.835,216.665 86.1,216.4 88,216.4 v1(89.2,215.2)
NetSB5_2: SB5.2 U8.F2 | length 21.9
  Top Layer w0.1: v1(89.5,213) SB5.2@90.6,213
  Top Layer w0.2: U8.F2@84.5,214.825 v3(84.66,214.665)
  Bottom Layer w0.1: v3(84.66,214.665) 86.1,213.225 86.1,207.1 88,205.2 89.3,205.2 90.1,206 90.1,208.5 89.5,209.1 v1(89.5,213)
NetSB6_2: SB6.2 U8.H2 | length 7.6
  Top Layer w0.1: U8.H2@85.5,214.825 85.9,214.425 85.9,213.8 86.089,213.611 87.989,213.611 88.8,212.8 88.8,211.7 89.2,211.3 SB6.2@90.6,211.3
NetSB7_2: SB7.2 U8.D3 | length 8.4
  Top Layer w0.1: SB7.2@81.291,208.534 v1(81.291,209.648)
  Top Layer w0.2: v3(83.34,215.165) U8.D3@83.5,215.325
  Bottom Layer w0.1: v1(81.291,209.648) 82.134,210.491 82.134,214.281 82.009,214.405 82.009,214.869 82.305,215.165 v3(83.34,215.165)
NetSB9_2: SB9.2 U8.G1 | length 6.3
  Top Layer w0.1: U8.G1@85,214.325 85,213.5 85.242,213.258 85.242,210.86 86.189,209.913 SB9.2@86.189,208.534
NetSB10_2: SB10.2 U8.E4 | length 10.8
  Top Layer w0.1: SB10.2@87.821,208.534 v1(87.821,209.729)
  Top Layer w0.2: U8.E4@84,215.825 v3(84.16,215.665)
  Bottom Layer w0.1: v3(84.16,215.665) 84.84,215.665 84.982,215.807 86.593,215.807 88.2,214.2 88.2,210.108 v1(87.821,209.729)
NetSB38_2: SB38.2 U10.6 | length 14.6
  Top Layer w0.1: SB38.2@172.726,153.692 172.726,156.834 173.221,157.328 173.221,166.616 173.66,167.055 U10.6@174.47,167.055
NetSB56_2: SB56.2 SB57.2 U12.13 | length 6.5
  Top Layer w0.1: U12.13@19.75,146.125 21.589,146.125 22.25,145.464 SB56.2@22.25,143.275 SB57.2@22.25,141.725
NetTP1_1: TP1.1 U5.10 | length 4.3
  Top Layer w0.1: U5.10@154.325,240.315 154.325,242.85 TP1.1@155.6,244.125 TP1.1@155.595,244.12
NetTP10_1: TP10.1 U8.C5 | length 8.5
  Top Layer w0.2: v3(82.84,216.485) U8.C5@83,216.325
  Bottom Layer w0.1: TP10.1@76.422,218.644 76.422,218.541 77.363,217.6 82.718,217.6 83.175,217.143 83.175,216.82 v3(82.84,216.485)
NetTP11_1: TP11.1 U8.B5 | length 7.1
  Top Layer w0.2: v3(82.34,216.485) U8.B5@82.5,216.325
  Bottom Layer w0.1: TP11.1@76.422,216.069 77.278,216.925 79.275,216.925 80.27,215.93 81.785,215.93 v3(82.34,216.485)
NetTP12_1: TP12.1 U9.42 | length 2.7
  Top Layer w0.1: U9.42@21.425,203.875 21.425,203.35 21.874,202.9 v1(22.289,202.9)
  Bottom Layer w0.1: TP12.1@21.169,202.901 v1(22.289,202.9)
NetTP22_1: TP22.1 U20.26 | length 3
  Top Layer w0.1: v1(72.692,108.706) 72.692,108.199 73.041,107.85 U20.26@73.85,107.85
  Bottom Layer w0.1: v1(72.692,108.706) 72.723,108.675 TP22.1@73.85,108.675
NetTP23_1: TP23.1 U20.28 | length 2.6
  Top Layer w0.1: v1(72.744,106.577) 73.017,106.85 U20.28@73.85,106.85
  Bottom Layer w0.1: v1(72.744,106.577) 73.228,106.092 73.592,106.092 TP23.1@73.85,106.35
NetU8_G3: U8.G3 U20.15 | length 123.3
  Top Layer w0.1: U20.15@79.85,109.85 79.847,109.853 79.847,110.562 79.982,110.697 82.823,110.697 84.148,112.022 v1(84.148,115.102) ; v1(88.93,205.875) 89.907,204.898 89.907,147.67 94.993,142.584 94.993,117.335 v1(94.981,117.323)
  Top Layer w0.2: U8.G3@85,215.325 v3(85.16,215.165)
  Bottom Layer w0.1: v1(84.148,115.102) 92.759,115.102 v1(94.981,117.323) ; v3@85.16,215.175 86.258,215.175 87.088,214.344 87.088,207.716 v1(88.93,205.875)
NJTRST: CN10.102 CN14.3 U10.21 U13.4 | length 93.6
  Top Layer w0.1: CN10.102@136.87,151.25 138.382,151.25 138.515,151.117 139.846,151.117 140.469,150.495 v1(142.009,150.495) ; U13.4@155.8,143.3 154.616,143.3 v1(154.609,143.294) 154.609,146.026 166.46,157.877 166.46,175.638 172.165,181.343 178.853,181.343 180.69,179.506 180.69,172.237 180.793,172.135 U10.21@181.53,172.135
  Top Layer w0.2: U13.4@155.8,143.3 156.154,143.3 156.769,143.915 CN14.3@162.23,143.915
  Bottom Layer w0.1: v1(142.009,150.495) 142.009,148.264 147.789,142.484 153.8,142.484 v1(154.609,143.294)
NOTOC1: U21.8 U22.13 | length 27.8
  Top Layer w0.1: U22.13@32.325,98.8 32.325,95.542 34.951,92.916 45.342,92.916 v1(45.713,92.546) ; v1(45.74,101.466) U21.8@45.74,102.482
  Bottom Layer w0.1: v1(45.713,92.546) 45.74,92.573 v1(45.74,101.466)
NOTOC2: U21.5 U22.17 | length 29.6
  Top Layer w0.1: U22.17@34.325,98.8 34.375,98.75 34.375,98.271 34.48,98.166 35.76,98.166 39.802,94.123 v1(46.657,94.123) ; U21.5@45.74,106.292 45.773,106.325 v1(47.722,106.325)
  Bottom Layer w0.1: v1(46.657,94.123) 48.191,95.657 48.191,105.856 v1(47.722,106.325)
NOTOC3: U22.19 U23.8 | length 12
  Top Layer w0.1: U22.19@35.575,99.55 36.119,99.55 36.25,99.419 36.25,98.86 39.266,95.844 U23.8@45.74,95.844
NOTOC4: U22.21 U23.5 | length 12.2
  Top Layer w0.1: U22.21@35.575,100.55 36.281,100.55 36.832,99.998 36.832,99.193 37.805,98.22 42.811,98.22 44.245,99.654 U23.5@45.74,99.654
NRST: CN10.17 CN14.15 SB62.1 U10.9 U16.5 | length 272.8
  Top Layer w0.1: SB62.1@37.125,130.05 43.246,130.05 46.775,126.521 51.638,126.521 v1(57.003,121.156) ; CN10.17@131.13,177.25 129.038,177.25 128.171,178.117 128.171,180.558 v1(132.004,184.391) ; v1(154.582,134.409) 154.59,134.4 U16.5@155.8,134.4 ; U16.5@156.065,134.4 U16.5@156.075,134.39 ; v1(160.14,145.46) 160.14,147.522 168.545,155.928 168.545,174.166 173.691,179.312 v1(178.308,179.312) 179.463,178.156 179.463,169.42 180.559,168.325 U10.9@181.53,168.325
  Top Layer w0.2: U16.5@155.8,134.4 U16.5@156.065,134.4 ; U16.5@156.075,134.39 156.075,133.305 160.705,128.675 CN14.15@162.23,128.675
  Bottom Layer w0.1: v1(57.003,121.156) 66.802,121.156 75.594,129.948 ; 75.644,129.948 76.068,129.524 86.849,129.524 87.275,129.95 91.64,129.95 96.099,134.409 v1(154.582,134.409) 155.844,133.146 158.742,133.146 160.14,134.544 v1(160.14,145.46) ; v1(132.004,184.391) 133.68,184.391 134.975,183.096 139.165,183.096 140.478,184.409 173.211,184.409 v1(178.308,179.312)
OTG_ID: CN9.98 CN16.4 Z5.4 | length 80
  Top Layer w0.1: CN16.4@4.125,125.65 5.065,125.65 5.277,125.863 v1(5.284,125.863) ; v1(64.043,142.233) 64.077,142.233 64.518,142.674 64.518,151.609 65.159,152.25 CN9.98@66.87,152.25
  Bottom Layer w0.1: v1(5.284,125.863) 5.683,125.464 Z5.4@5.984,125.464 ; 6.284,125.523 6.284,126.818 7.141,127.674 9.751,127.674 ; 9.557,127.671 21.499,127.671 32.105,138.276 60.086,138.276 v1(64.043,142.233)
OTG_VBUS: CN9.100 R97.1 R102.1 | length 82.3
  Top Layer w0.1: R102.1@9.437,114.72 9.437,116.08 9.429,116.088 9.997,116.088 10.486,116.577 10.486,121.112 v1(16.431,127.058) ; v1(64.542,140.724) 64.758,140.94 64.758,151.275 65.234,151.75 CN9.100@66.87,151.75
  Bottom Layer w0.1: v1(16.431,127.058) 21.76,127.058 32.416,137.714 61.532,137.714 v1(64.542,140.724)
PA0_WKUP: CN10.15 R118.1 | length 117.5
  Top Layer w0.1: R118.1@87.375,102.71 v1(88.246,102.71) ; v1(101.702,105.258) 101.702,120.106 ; 101.711,120.106 101.708,120.109 101.708,121.38 99.477,123.61 99.477,126.452 108.432,135.407 v1(108.432,179.353) ; v1(129.534,177.745) 131.125,177.745 CN10.15@131.13,177.75
  Bottom Layer w0.1: v1(88.246,102.71) 99.153,102.71 v1(101.702,105.258) ; v1(108.432,179.353) 127.14,179.353 128.747,177.745 v1(129.534,177.745)
PA13: CN9.25 SB56.1 | length 62.9
  Top Layer w0.1: SB56.1@23.35,143.275 v1(24.738,143.275) ; v1(47.228,150.727) 48.327,151.827 48.327,170.089 54.612,176.373 58.464,176.373 59.587,175.25 CN9.25@61.13,175.25
  Bottom Layer w0.1: v1(24.738,143.275) 24.738,143.755 31.71,150.727 v1(47.228,150.727)
PA14: CN9.27 SB18.2 | length 117.5
  Top Layer w0.1: CN9.27@61.13,174.75 62.697,174.75 v1(62.7,174.753) ; v1(169.707,169.575) SB18.2@171.05,169.575
  Bottom Layer w0.1: v1(62.7,174.753) 76.938,174.753 83.485,181.3 140.445,181.3 142.4,179.345 159.937,179.345 v1(169.707,169.575)
PF12: CN9.57 SB20.2 | length 3.3
  Top Layer w0.1: SB20.2@57.817,167.225 57.842,167.25 CN9.57@61.13,167.25
PHYRSTB: CN6.54 R73.2 U9.38 | length 31.2
  Top Layer w0.1: U9.38@19.425,203.875 19.425,202.653 19.036,202.265 19.036,201.488 R73.2@19.036,200.412 19.036,199.419 19.041,199.414 19.146,199.414 19.851,198.709 19.851,196.651 v1(20.397,196.104) ; v1(29.135,195.503) 29.135,183.292 29.45,182.977 CN6.54@29.45,182
  Bottom Layer w0.1: v1(20.397,196.104) 20.999,195.503 v1(29.135,195.503)
PRTPWR1: U21.3 U22.12 | length 36.6
  Top Layer w0.1: U22.12@31.825,98.8 31.825,98.128 32.039,97.914 32.039,95.257 34.767,92.529 44.072,92.529 44.973,91.628 v1(48.544,91.628) ; v1(49.118,105.022) U21.3@50.49,105.022
  Bottom Layer w0.1: v1(48.544,91.628) 49.118,92.203 v1(49.118,105.022)
PRTPWR2: U21.4 U22.16 | length 31.8
  Top Layer w0.1: U22.16@33.825,98.8 33.825,98.105 34.02,97.91 35.475,97.91 40.101,93.284 v1(48.158,93.284) ; v1(49.092,106.292) U21.4@50.49,106.292
  Bottom Layer w0.1: v1(48.158,93.284) 48.55,93.676 48.55,105.75 v1(49.092,106.292)
PRTPWR3: U22.18 U23.3 | length 19.2
  Top Layer w0.1: U22.18@34.825,98.8 35.743,98.8 39.807,94.736 46.361,94.736 48.277,96.652 48.277,97.316 49.345,98.384 U23.3@50.49,98.384
PRTPWR4: U22.20 U23.4 | length 17
  Top Layer w0.1: U22.20@35.575,100.05 36.168,100.05 36.536,99.682 36.536,99.005 37.763,97.778 43.035,97.778 44.28,99.023 48.183,99.023 48.814,99.654 U23.4@50.49,99.654
QSPI_BK1_IO0: CN9.76 U14.D3 | length 32.6
  Top Layer w0.1: CN9.76@66.87,157.75 66.92,157.7 70.655,157.7 77.568,150.786 77.568,135.62 77.95,135.238 77.95,133.595 77.73,133.375 76.95,133.375 U14.D3@76.575,133.75
QSPI_BK1_IO1: CN9.78 U14.D2 | length 30
  Top Layer w0.1: CN9.78@66.87,157.25 66.92,157.2 70.492,157.2 77.068,150.624 77.068,134.257 U14.D2@77.575,133.75
QSPI_BK1_IO2: CN9.80 U14.C4 | length 30.4
  Top Layer w0.1: CN9.80@66.87,156.75 66.92,156.7 70.329,156.7 76.568,150.461 76.568,135.274 76.2,134.905 76.2,133.375 U14.C4@75.575,132.75
QSPI_BK1_IO3: CN9.82 U14.D4 | length 28.7
  Top Layer w0.1: CN9.82@66.87,156.25 66.92,156.2 70.16,156.2 76.068,150.292 76.068,136.172 75.2,135.303 75.2,134.125 U14.D4@75.575,133.75
QSPI_BK1_NCS: CN9.74 SB59.1 | length 30
  Top Layer w0.1: CN9.74@66.87,158.25 66.92,158.2 70.802,158.2 78.068,150.933 78.068,140.039 81.155,136.952 81.155,136.444
QSPI_BK2_IO0: CN9.64 U15.D3 | length 41
  Top Layer w0.1: CN9.64@66.87,160.75 71.049,160.75 85.454,146.345 85.454,139.316 89.807,134.963 89.807,133.557 89.471,133.221 88.804,133.221 U15.D3@88.275,133.75
QSPI_BK2_IO1: CN9.66 U15.D2 | length 38.2
  Top Layer w0.1: CN9.66@66.87,160.25 71.042,160.25 84.953,146.339 84.953,138.996 88.788,135.161 88.788,134.237 U15.D2@89.275,133.75
QSPI_BK2_IO2: CN9.68 U15.C4 | length 38.4
  Top Layer w0.1: CN9.68@66.87,159.75 71.049,159.75 84.498,146.301 84.498,138.718 87.85,135.365 87.85,133.325 U15.C4@87.275,132.75
QSPI_BK2_IO3: CN9.70 U15.D4 | length 36.4
  Top Layer w0.1: CN9.70@66.87,159.25 70.97,159.25 84.027,146.193 84.027,138.381 86.782,135.626 86.782,134.243 U15.D4@87.275,133.75
QSPI_BK2_NCS: CN9.72 SB60.1 | length 31.6
  Top Layer w0.1: CN9.72@66.87,158.75 70.92,158.75 83.508,146.162 SB60.1@83.508,136.444
QSPI_CLK: CN9.62 U14.B2 U15.B2 | length 57.8
  Top Layer w0.13: CN9.62@66.87,161.25 71.493,161.25 86.159,146.583 86.159,139.791 90.942,135.008 v1(90.942,132.258) 89.783,132.258 U15.B2@89.275,131.75 ; U14.B2@77.575,131.75 v1(78.378,130.947)
  Bottom Layer w0.13: v1(78.378,130.947) 79.69,132.258 v1(90.942,132.258)
QSPI_RESETn: C68.2 R90.2 U14.A4 U15.A4 U17.2 | length 21.9
  Top Layer w0.1: U14.A4@75.575,130.75 75.575,129.3 75.875,129 87,129 ; U17.2@82.7,126.1 86.8,126.1 87,126.3 87,129 ; U15.A4@87.275,130.75 87.275,130.15 87,129.875 87,129
RJ45_D1_N: CN3.2 U9.6 | length 24.6
  Top Layer w0.1: U9.6@21.925,212.675 21.925,213 22.06,213.135 22.06,224.16 24.225,226.325 24.225,234.275 24.475,234.525 24.475,236.22 CN3.2@24.445,236.25
RJ45_D1_P: CN3.1 U9.5 | length 24.1
  Top Layer w0.1: U9.5@22.425,212.675 22.425,212.975 22.29,213.11 22.29,224.065 24.455,226.23 24.455,234.18 24.725,234.45 24.975,234.45 CN3.1@25.715,233.71
RJ45_D2_N: CN3.4 U9.9 | length 24.2
  Top Layer w0.1: U9.9@20.425,212.675 20.425,213 20.56,213.135 20.56,225.31 21.7,226.45 21.7,234.25 21.905,234.455 CN3.4@21.905,236.25
RJ45_D2_P: CN3.3 U9.8 | length 23.6
  Top Layer w0.1: U9.8@20.925,212.675 20.925,213.025 20.79,213.16 20.79,225.215 21.93,226.355 21.93,234.155 22.075,234.3 22.5,234.3 23.09,233.71 CN3.3@23.175,233.71
RJ45_D3_N: CN3.8 U9.12 | length 24.8
  Top Layer w0.1: CN3.8@16.825,236.25 16.9,236.175 16.9,234.625 16.575,234.3 16.575,228.275 19.06,225.79 19.06,213.135 18.925,213 U9.12@18.925,212.675
RJ45_D3_P: CN3.7 U9.11 | length 24.3
  Top Layer w0.1: CN3.7@18.095,233.71 18.04,233.71 17.35,234.4 17,234.4 16.805,234.205 16.805,228.37 19.29,225.885 19.29,213.135 19.425,213 U9.11@19.425,212.675
RJ45_D4_N: CN3.10 U9.15 | length 25.4
  Top Layer w0.1: CN3.10@14.285,236.25 14.337,236.198 14.337,234.738 13.895,234.295 13.895,228.605 17.56,224.94 17.56,213.135 17.425,213 U9.15@17.425,212.675
RJ45_D4_P: CN3.9 U9.14 | length 24.9
  Top Layer w0.1: CN3.9@15.555,233.71 14.84,234.425 14.35,234.425 14.125,234.2 14.125,228.7 17.79,225.035 17.79,213.135 17.925,213 U9.14@17.925,212.675
RXCLK: R56.2 R74.1 U9.24 | length 29.4
  Top Layer w0.13: R56.2@13.775,208.575 R56.2@13.775,208.525 ; R74.1@15.046,184.761 14.972,184.761 11.468,188.265 11.468,207.102 12.369,208.003 13.312,208.003 13.775,208.466 R56.2@13.775,208.525 ; U9.24@16.275,208.525 16.231,208.569 13.819,208.569 R56.2@13.775,208.525
RXDLY: R64.1 U9.28 | length 3
  Top Layer w0.1: R64.1@13.775,205.275 15.025,206.525 U9.28@16.275,206.525
RXDV_PHY_AD2: CN6.16 R45.2 U9.18 | length 35.9
  Top Layer w0.13: v1(11.903,209.222) 10.952,208.27 10.952,187.82 14.25,184.522 CN6.16@14.25,182 ; R45.2@14.875,213.075 15.018,213.075 15.018,212.333 v1(15.002,212.317) 15.795,211.525 U9.18@16.275,211.525
  Bottom Layer w0.13: v1(11.903,209.222) 11.907,209.222 v1(15.002,212.317)
RXER_AN1: R71.1 U9.30 | length 3.7
  Top Layer w0.1: R71.1@13.775,203.125 13.775,203.17 14.821,204.215 14.821,204.561 15.785,205.525 U9.30@16.275,205.525
SAI2_FSA: CN10.112 SB11.1 SB63.2 SB65.2 | length 166.1
  Top Layer w0.1: SB11.1@82.923,207.434 82.924,205.385 86.116,202.192 86.116,154.074 86.287,153.903 v1(86.287,153.016) ; CN10.112@136.87,148.75 138.255,148.75 140.812,146.193 v1(140.812,141.324) 140.812,129.941 158.414,112.339 158.414,111.336 159.727,110.023 SB63.2@159.837,110.023 SB65.2@159.836,108.472
  Bottom Layer w0.1: v1(86.287,153.016) 86.374,153.016 98.362,141.028 140.516,141.028 v1(140.812,141.324)
SAI2_FSB: CN10.14 U8.F4 | length 87
  Top Layer w0.1: v1(94.8,213.6) 109.5,198.9 v1(110.6,198.9) ; CN10.14@136.87,178.25 140.35,178.25 141.4,179.3 v1(141.4,192.6)
  Top Layer w0.2: U8.F4@84.5,215.825 v3(84.66,215.985)
  Bottom Layer w0.1: v3(84.66,215.985) 84.66,216.16 84.965,216.465 85.335,216.465 85.7,216.1 87,216.1 88.5,214.6 88.5,214.1 89,213.6 v1(94.8,213.6) ; v1(110.6,198.9) 110.6,196.7 114.7,192.6 v1(141.4,192.6)
SAI2_MCLKA: CN10.110 SB7.1 SB53.2 | length 125.9
  Top Layer w0.1: SB7.1@81.291,207.434 81.291,206.101 85.554,201.838 v1(85.554,154.631) ; CN10.110@136.87,149.25 138.603,149.25 139.293,148.561 SB53.2@140.303,148.561 140.303,147.282 141.353,146.233 v1(141.353,143.293)
  Bottom Layer w0.1: v1(85.554,154.631) 98.604,141.581 139.598,141.581 141.31,143.293 v1(141.353,143.293)
SAI2_MCLKB: CN10.16 U8.E1 | length 93.3
  Top Layer w0.1: v1(93.8,204.5) 101.1,197.2 v1(111.2,197.2) ; CN10.16@136.87,177.75 140.95,177.75 141.9,178.7 v1(141.9,193.4)
  Top Layer w0.2: U8.E1@84,214.3 v3(84.16,214.14)
  Bottom Layer w0.1: v3(84.16,214.14) 85.6,212.7 85.6,210.7 85.1,210.2 84.2,210.2 83.9,209.9 83.9,206.8 86.2,204.5 v1(93.8,204.5) ; v1(111.2,197.2) 115.3,193.1 140.3,193.1 140.6,193.4 v1(141.9,193.4)
SAI2_SCKA: CN10.114 SB9.1 SB66.2 SB67.2 | length 165.6
  Top Layer w0.1: SB9.1@86.189,207.434 86.189,206.027 87.115,205.1 87.115,154.823 87.432,154.506 v1(88.557,154.506) ; CN10.114@136.87,148.25 138.22,148.25 140.021,146.449 v1(140.021,144.365) 140.021,129.934 157.813,112.142 157.813,108.263 159.755,106.321 SB66.2@159.837,106.321 SB67.2@159.836,104.769
  Bottom Layer w0.1: v1(88.557,154.506) 88.557,153.899 99.485,142.971 137.771,142.971 139.165,144.365 v1(140.021,144.365)
SAI2_SDA: CN10.118 SB10.1 SB73.2 SB75.2 | length 170.2
  Top Layer w0.1: v1(87.605,155.209) 87.605,207.218 SB10.1@87.821,207.434 ; CN10.118@136.87,147.25 138.112,147.25 138.893,146.469 138.877,146.453 v1(138.877,142.178) 138.877,129.37 156.585,111.661 156.585,105.062 158.448,103.198 158.448,100.246 159.779,98.915 SB73.2@159.837,98.915 SB75.2@159.836,97.364
  Bottom Layer w0.1: v1(87.605,155.209) 87.605,153.383 98.811,142.178 v1(138.877,142.178)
